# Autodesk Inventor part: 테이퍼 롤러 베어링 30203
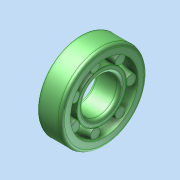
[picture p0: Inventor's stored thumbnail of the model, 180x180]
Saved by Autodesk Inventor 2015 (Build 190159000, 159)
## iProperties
Created: 2026-02
Part Number: 테이퍼 롤러 베어링 30203
Material: 일반
Document SubType Name: Modeling
Designer: Administrator
Density: 1 g/cm^3
Appearance: 기본값
Author: Administrator
Author: jhkim
Description: 테이퍼 롤러 베어링
Creation Date: 2026-01-30
Sending System: Autodesk Inventor 2026
Preprocessor: ST-DEVELOPER v20.1
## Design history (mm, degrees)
node "테이퍼 롤러 베어링 302031"
body "Solid1"
node "Solid1_1"
node "기준1"
node "기준2"
